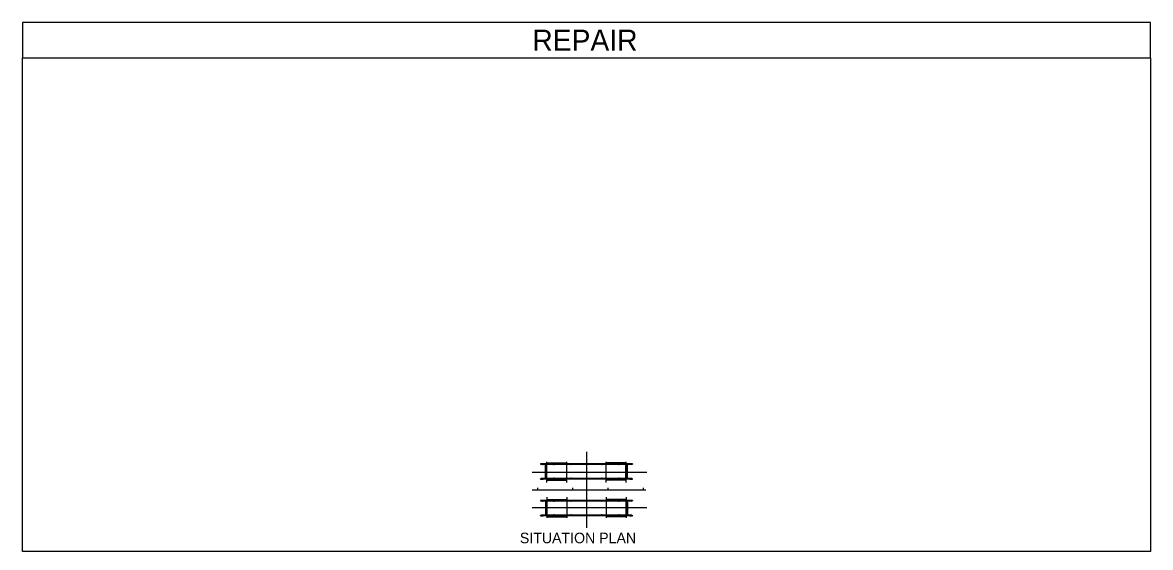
# Model space of a CAD drawing. Extents: x -6598 to 6602, y -3155 to 3145.
# Drawn here: x 3402 to 6602, y 1657 to 3145 of the extents above; entities that cross this region are included whole.
import ezdxf

# ---------------------------------------------------------------- set-up
doc = ezdxf.new("R2010")
doc.units = 0
for name, color, linetype in [('BridgeExistingStructure', 7, 'Continuous'), ('DsnShtMinorGrid01', 7, 'Continuous'), ('PC_CONCRETE', 7, 'Continuous'), ('Revetment', 7, 'Continuous'), ('ShtPlotShapeBatchPrint', 7, 'Continuous')]:
    doc.layers.add(name, color=color, linetype=linetype)

msp = doc.modelspace()

# ---------------------------------------------------------------- linework, layer by layer
at = {"layer": 'BridgeExistingStructure'}
for p, q in [((4871, 1893.9), (4871, 1893)), ((4871, 1893.9), (4878.4, 1893.9)), ((4873, 1892.5), (4871, 1893)), ((4878.4, 1894), (4871.4, 1894)), ((4871.4, 1894), (4871.4, 1893.9)), ((4886.7, 1892.5), (4873, 1892.5)), ((4876.6, 1892.5), (4878.4, 1892.4)), ((4886.7, 1894), (4878.4, 1894)), ((4878.4, 1893.7), (4878.4, 1893.9)), ((4886.7, 1893.7), (4878.4, 1893.7)), ((4885.5, 1892.4), (4878.4, 1892.4)), ((4888.1, 1892.4), (4888.1, 1894)), ((5112.9, 1894), (4888.1, 1894)), ((5112.9, 1893.7), (4888.1, 1893.7)), ((5112.9, 1892.5), (4888.1, 1892.5)), ((5124.7, 1894), (5116.4, 1894)), ((5124.7, 1893.7), (5116.4, 1893.7)), ((5130.2, 1892.5), (5116.4, 1892.5)), ((5124.7, 1892.4), (5117.7, 1892.4)), ((5124.7, 1894), (5131.7, 1894)), ((5132.2, 1893.9), (5124.7, 1893.9)), ((5124.7, 1893.7), (5124.7, 1893.9)), ((5126.5, 1892.5), (5124.7, 1892.4)), ((5130.2, 1892.5), (5132.2, 1893)), ((5131.7, 1894), (5131.7, 1893.9)), ((5132.2, 1893.9), (5132.2, 1893)), ((4873, 1852.2), (4871, 1851.7)), ((4871, 1850.9), (4871, 1851.7)), ((4871, 1850.9), (4878.4, 1850.9)), ((4871.4, 1850.7), (4871.4, 1850.9)), ((4878.4, 1850.7), (4871.4, 1850.7)), ((4886.7, 1852.2), (4873, 1852.2)), ((4876.6, 1852.2), (4878.4, 1852.4)), ((4885.5, 1852.4), (4878.4, 1852.4)), ((4878.4, 1851.4), (4878.4, 1850.9)), ((4886.7, 1851.4), (4878.4, 1851.4)), ((4886.7, 1850.7), (4878.4, 1850.7)), ((4888.1, 1850.7), (4888.1, 1852.4)), ((5112.9, 1852.2), (4888.1, 1852.2)), ((5112.9, 1851.4), (4888.1, 1851.4)), ((5112.9, 1850.7), (4888.1, 1850.7)), ((5130.2, 1852.2), (5116.4, 1852.2)), ((5124.7, 1851.4), (5116.4, 1851.4)), ((5124.7, 1850.7), (5116.4, 1850.7)), ((5124.7, 1852.4), (5117.7, 1852.4)), ((5126.5, 1852.2), (5124.7, 1852.4)), ((5124.7, 1851.4), (5124.7, 1850.9)), ((5132.2, 1850.9), (5124.7, 1850.9)), ((5124.7, 1850.7), (5131.7, 1850.7)), ((5130.2, 1852.2), (5132.2, 1851.7)), ((5131.7, 1850.7), (5131.7, 1850.9)), ((5132.2, 1850.9), (5132.2, 1851.7)), ((4871, 1789.9), (4871, 1789)), ((4871, 1789.9), (4878.4, 1789.9)), ((4873, 1788.5), (4871, 1789)), ((4878.4, 1790), (4871.4, 1790)), ((4871.4, 1790), (4871.4, 1789.9)), ((4886.7, 1788.5), (4873, 1788.5)), ((4876.6, 1788.5), (4878.4, 1788.4)), ((4886.7, 1790), (4878.4, 1790)), ((4878.4, 1789.4), (4878.4, 1789.9)), ((4886.7, 1789.4), (4878.4, 1789.4)), ((4885.5, 1788.4), (4878.4, 1788.4)), ((5112.9, 1790), (4888.1, 1790)), ((5112.9, 1789.4), (4888.1, 1789.4)), ((5112.9, 1788.5), (4888.1, 1788.5)), ((5112.9, 1788.4), (4888.1, 1788.4)), ((5124.7, 1790), (5116.4, 1790)), ((5124.7, 1789.4), (5116.4, 1789.4)), ((5130.2, 1788.5), (5116.4, 1788.5)), ((5124.7, 1788.4), (5117.7, 1788.4)), ((5124.7, 1790), (5131.7, 1790)), ((5132.2, 1789.9), (5124.7, 1789.9)), ((5124.7, 1789.4), (5124.7, 1789.9)), ((5126.5, 1788.5), (5124.7, 1788.4)), ((5130.2, 1788.5), (5132.2, 1789)), ((5131.7, 1790), (5131.7, 1789.9)), ((5132.2, 1789.9), (5132.2, 1789)), ((4873, 1748.2), (4871, 1747.7)), ((4871, 1746.9), (4871, 1747.7)), ((4871, 1746.9), (4878.4, 1746.9)), ((4871.4, 1746.7), (4871.4, 1746.9)), ((4878.4, 1746.7), (4871.4, 1746.7)), ((4886.7, 1748.2), (4873, 1748.2)), ((4876.6, 1748.2), (4878.4, 1748.4)), ((4885.5, 1748.4), (4878.4, 1748.4)), ((4878.4, 1747), (4878.4, 1746.9)), ((4886.7, 1747), (4878.4, 1747)), ((4886.7, 1746.7), (4878.4, 1746.7)), ((5112.9, 1748.4), (4888.1, 1748.4)), ((5112.9, 1748.2), (4888.1, 1748.2)), ((5112.9, 1747), (4888.1, 1747)), ((5112.9, 1746.7), (4888.1, 1746.7)), ((5130.2, 1748.2), (5116.4, 1748.2)), ((5124.7, 1747), (5116.4, 1747)), ((5124.7, 1746.7), (5116.4, 1746.7)), ((5124.7, 1748.4), (5117.7, 1748.4)), ((5126.5, 1748.2), (5124.7, 1748.4)), ((5124.7, 1747), (5124.7, 1746.9)), ((5132.2, 1746.9), (5124.7, 1746.9)), ((5124.7, 1746.7), (5131.7, 1746.7)), ((5130.2, 1748.2), (5132.2, 1747.7)), ((5131.7, 1746.7), (5131.7, 1746.9)), ((5132.2, 1746.9), (5132.2, 1747.7))]:
    msp.add_line(p, q, dxfattribs=at)
at = {"layer": 'DsnShtMinorGrid01'}
for p, q in [((5001.5, 1927.8), (5001.5, 1712.4)), ((4847.8, 1870.4), (5172.5, 1870.4)), ((4862.3, 1825.4), (4862.3, 1820.4)), ((4962.3, 1825.4), (4962.3, 1820.4)), ((5062.3, 1825.4), (5062.3, 1820.4)), ((5162.3, 1825.4), (5162.3, 1820.4)), ((4847.8, 1820.4), (5169.9, 1820.4)), ((4847.8, 1770.4), (5172.5, 1770.4))]:
    msp.add_line(p, q, dxfattribs=at)
at = {"layer": 'PC_CONCRETE'}
for p, q in [((4885.5, 1852.4), (4885.5, 1892.4)), ((4886.7, 1892.4), (4885.5, 1892.4)), ((4886.7, 1894), (4886.7, 1850.7)), ((4888, 1894), (4886.7, 1894)), ((4888, 1893.7), (4886.7, 1893.7)), ((4888, 1892.5), (4886.7, 1892.5)), ((4888, 1892.4), (4886.7, 1892.4)), ((4888, 1850.7), (4888, 1894)), ((5114.9, 1892.4), (4888.1, 1892.4)), ((4888.1, 1852.4), (4888.1, 1892.4)), ((4909.4, 1891.4), (4908.8, 1891.4)), ((4958.4, 1891.4), (4957.8, 1891.4)), ((5045.4, 1891.4), (5044.8, 1891.4)), ((5094.4, 1891.4), (5093.8, 1891.4)), ((5114.9, 1894), (5112.9, 1894)), ((5112.9, 1850.7), (5112.9, 1894)), ((5114.9, 1893.7), (5112.9, 1893.7)), ((5114.9, 1892.5), (5112.9, 1892.5)), ((5114.9, 1850.7), (5114.9, 1894)), ((5115.1, 1850.7), (5115.1, 1894)), ((5116.4, 1894), (5115.1, 1894)), ((5116.4, 1893.7), (5115.1, 1893.7)), ((5116.4, 1892.5), (5115.1, 1892.5)), ((5116.4, 1892.4), (5115.1, 1892.4)), ((5116.4, 1850.7), (5116.4, 1894)), ((5117.7, 1892.4), (5116.4, 1892.4)), ((5117.7, 1852.4), (5117.7, 1892.4)), ((4888, 1852.4), (4885.5, 1852.4)), ((4888, 1852.2), (4886.7, 1852.2)), ((4888, 1851.4), (4886.7, 1851.4)), ((4888, 1850.7), (4886.7, 1850.7)), ((5114.9, 1852.4), (4888.1, 1852.4)), ((4909.4, 1853.4), (4908.8, 1853.4)), ((4958.4, 1853.4), (4957.8, 1853.4)), ((5045.4, 1853.4), (5044.8, 1853.4)), ((5094.4, 1853.4), (5093.8, 1853.4)), ((5114.9, 1852.2), (5112.9, 1852.2)), ((5114.9, 1851.4), (5112.9, 1851.4)), ((5114.9, 1850.7), (5112.9, 1850.7)), ((5117.7, 1852.4), (5115.1, 1852.4)), ((5116.4, 1852.2), (5115.1, 1852.2)), ((5116.4, 1851.4), (5115.1, 1851.4)), ((5116.4, 1850.7), (5115.1, 1850.7)), ((4888, 1788.4), (4885.5, 1788.4)), ((4885.5, 1788.4), (4885.5, 1748.4)), ((4888, 1790), (4886.7, 1790)), ((4886.7, 1746.7), (4886.7, 1790)), ((4888, 1789.4), (4886.7, 1789.4)), ((4888, 1788.5), (4886.7, 1788.5)), ((4888, 1790), (4888, 1746.7)), ((4888.1, 1790), (4888.1, 1746.7)), ((4909.4, 1787.4), (4908.8, 1787.4)), ((4958.4, 1787.4), (4957.8, 1787.4)), ((5045.4, 1787.4), (5044.8, 1787.4)), ((5094.4, 1787.4), (5093.8, 1787.4)), ((5114.9, 1790), (5112.9, 1790)), ((5112.9, 1790), (5112.9, 1746.7)), ((5114.9, 1789.4), (5112.9, 1789.4)), ((5114.9, 1788.5), (5112.9, 1788.5)), ((5114.9, 1788.4), (5112.9, 1788.4)), ((5114.9, 1790), (5114.9, 1746.7)), ((5115.1, 1790), (5115.1, 1746.7)), ((5116.4, 1790), (5115.1, 1790)), ((5116.4, 1789.4), (5115.1, 1789.4)), ((5116.4, 1788.5), (5115.1, 1788.5)), ((5117.7, 1788.4), (5115.1, 1788.4)), ((5116.4, 1790), (5116.4, 1746.7)), ((5117.7, 1788.4), (5117.7, 1748.4)), ((4888, 1748.4), (4885.5, 1748.4)), ((4888, 1748.2), (4886.7, 1748.2)), ((4888, 1747), (4886.7, 1747)), ((4888, 1746.7), (4886.7, 1746.7)), ((4909.4, 1749.4), (4908.8, 1749.4)), ((4958.4, 1749.4), (4957.8, 1749.4)), ((5045.4, 1749.4), (5044.8, 1749.4)), ((5094.4, 1749.4), (5093.8, 1749.4)), ((5114.9, 1748.4), (5112.9, 1748.4)), ((5114.9, 1748.2), (5112.9, 1748.2)), ((5114.9, 1747), (5112.9, 1747)), ((5114.9, 1746.7), (5112.9, 1746.7)), ((5117.7, 1748.4), (5115.1, 1748.4)), ((5116.4, 1748.2), (5115.1, 1748.2)), ((5116.4, 1747), (5115.1, 1747)), ((5116.4, 1746.7), (5115.1, 1746.7))]:
    msp.add_line(p, q, dxfattribs=at)
for centre, start, end in [((4908.8, 1892.4), 180, 270), ((4909.4, 1892.4), 270, 0), ((4957.8, 1892.4), 180, 270), ((4958.4, 1892.4), 270, 0), ((5044.8, 1892.4), 180, 270), ((5045.4, 1892.4), 270, 0), ((5093.8, 1892.4), 180, 270), ((5094.4, 1892.4), 270, 0), ((4908.8, 1852.4), 90, 180), ((4909.4, 1852.4), 0, 90), ((4957.8, 1852.4), 90, 180), ((4958.4, 1852.4), 0, 90), ((5044.8, 1852.4), 90, 180), ((5045.4, 1852.4), 0, 90), ((5093.8, 1852.4), 90, 180), ((5094.4, 1852.4), 0, 90), ((4908.8, 1788.4), 180, 270), ((4909.4, 1788.4), 270, 0), ((4957.8, 1788.4), 180, 270), ((4958.4, 1788.4), 270, 0), ((5044.8, 1788.4), 180, 270), ((5045.4, 1788.4), 270, 0), ((5093.8, 1788.4), 180, 270), ((5094.4, 1788.4), 270, 0), ((4908.8, 1748.4), 90, 180), ((4909.4, 1748.4), 0, 90), ((4957.8, 1748.4), 90, 180), ((4958.4, 1748.4), 0, 90), ((5044.8, 1748.4), 90, 180), ((5045.4, 1748.4), 0, 90), ((5093.8, 1748.4), 90, 180), ((5094.4, 1748.4), 0, 90)]:
    msp.add_arc(centre, 1, start, end, dxfattribs=at)
at = {"layer": 'Revetment'}
for p, q in [((4888, 1894), (4888.1, 1894)), ((4890.6, 1894), (4890.6, 1897)), ((4890.6, 1897), (4943.6, 1897)), ((4943.6, 1897), (4943.6, 1894)), ((5058.3, 1897), (5058.3, 1894)), ((5112.6, 1897), (5058.3, 1897)), ((5112.6, 1894), (5112.6, 1897)), ((5114.9, 1894), (5115.1, 1894)), ((4888, 1850.7), (4888.1, 1850.7)), ((4890.6, 1850.7), (4890.6, 1847.7)), ((4890.6, 1847.7), (4943.6, 1847.7)), ((4943.6, 1847.7), (4943.6, 1850.7)), ((5058.3, 1847.7), (5058.3, 1850.7)), ((5112.6, 1847.7), (5058.3, 1847.7)), ((5112.6, 1850.7), (5112.6, 1847.7)), ((5114.9, 1850.7), (5115.1, 1850.7)), ((4890.6, 1793), (4943.6, 1793)), ((4890.6, 1790), (4890.6, 1793)), ((4943.6, 1793), (4943.6, 1790)), ((5058.3, 1793), (5058.3, 1790)), ((5112.6, 1793), (5058.3, 1793)), ((5112.6, 1790), (5112.6, 1793)), ((4890.6, 1746.7), (4890.6, 1743.7)), ((4890.6, 1743.7), (4943.6, 1743.7)), ((4943.6, 1743.7), (4943.6, 1746.7)), ((5058.3, 1743.7), (5058.3, 1746.7)), ((5112.6, 1743.7), (5058.3, 1743.7)), ((5112.6, 1746.7), (5112.6, 1743.7))]:
    msp.add_line(p, q, dxfattribs=at)
at = {"layer": 'ShtPlotShapeBatchPrint'}
for p, q in [((4889.1, 1841.2), (4889.1, 1899.5)), ((4946.1, 1841.2), (4946.1, 1899.5)), ((5057.1, 1841.2), (5057.1, 1899.5)), ((5114.1, 1841.2), (5114.1, 1899.5)), ((4889.1, 1799.5), (4889.1, 1741.2)), ((4946.1, 1799.5), (4946.1, 1741.2)), ((5057.1, 1799.5), (5057.1, 1741.2)), ((5114.1, 1799.5), (5114.1, 1741.2))]:
    msp.add_line(p, q, dxfattribs=at)
for points in [[(3401.6, 3045.4), (6601.6, 3045.4), (6601.6, 3145.4), (3401.6, 3145.4)], [(3401.6, 3045.4), (6601.6, 3045.4), (6601.6, 1645.4), (3401.6, 1645.4)]]:
    msp.add_lwpolyline(points, close=True, dxfattribs=at)

# ---------------------------------------------------------------- texts
for s, height, p in [('REPAIR', 60, (4847.8, 3065.4)), ('SITUATION PLAN', 30, (4812.5, 1668.7))]:
    msp.add_text(s, height=height, dxfattribs=at).set_placement(p)

doc.saveas('drawing.dxf')
